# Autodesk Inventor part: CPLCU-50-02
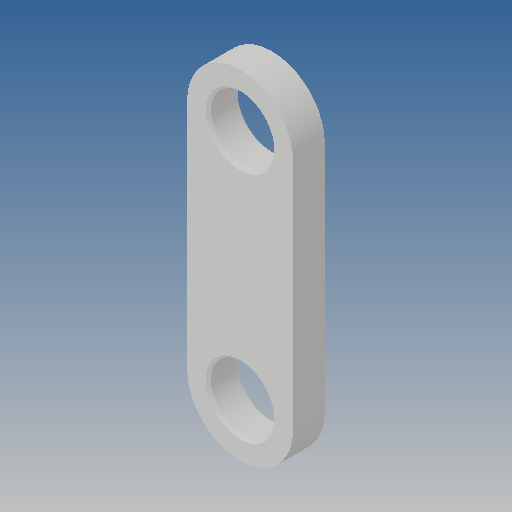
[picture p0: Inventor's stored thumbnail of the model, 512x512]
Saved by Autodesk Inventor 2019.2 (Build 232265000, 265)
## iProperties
Created: 2010-03
Part Number: CPLCU-50-02
Material: Ogólny
Document SubType Name: Modeling
Designer: CADENGINEERING4
Density: 1 g/cm^3
Appearance: Domyślna
Author: CADENGINEERING4
Revision Number: 3LAST_VERSION
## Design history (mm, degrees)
feature "Baza1"
node "Bryła1"
